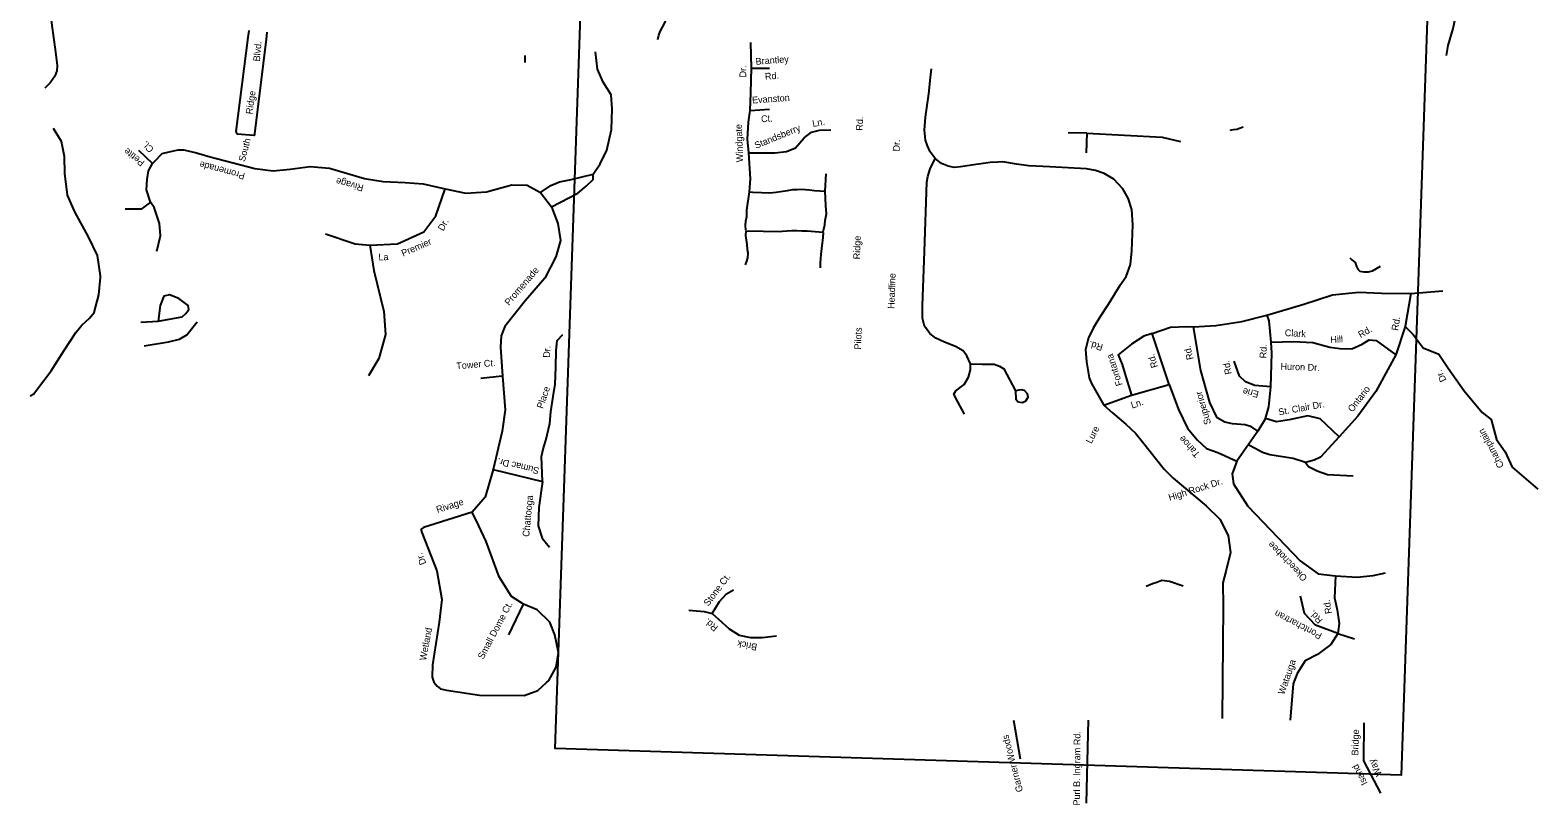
# Model space of a CAD drawing. Extents: x 2308163 to 2335412, y -96774 to 125428.
# Drawn here: x 2317543 to 2321199, y -15693 to -13815 of the extents above; entities that cross this region are included whole.
import ezdxf

# ---------------------------------------------------------------- set-up
doc = ezdxf.new("R2010")
doc.units = 0
for name, color, linetype in [('Old_Level_10', 7, 'Continuous'), ('Old_Level_35', 7, 'Continuous'), ('Old_Level_63', 7, 'Continuous')]:
    doc.layers.add(name, color=color, linetype=linetype)

msp = doc.modelspace()

# ---------------------------------------------------------------- linework, layer by layer
at = {"layer": 'Old_Level_35'}
for p, q in [((2318072, -13833), (2318074.1, -13816.2)), ((2318117.4, -13820.5), (2318115.4, -13837.3)), ((2318743.8, -13893.5), (2318743.3, -13876.6)), ((2319470.7, -14205.2), (2319473.7, -14163.5))]:
    msp.add_line(p, q, dxfattribs=at)
for points in [[(2319065.6, -13837.6), (2319067.4, -13827.6), (2319070.7, -13818.6), (2319081.2, -13799.3), (2319094.4, -13768.8), (2319113.5, -13720.3), (2319131.1, -13670.2), (2319159.1, -13602.4)], [(2317587.9, -13741.7), (2317588.9, -13749.8), (2317595.6, -13803.7), (2317603.9, -13862.2), (2317608.6, -13901.1), (2317608.2, -13914.1), (2317603.3, -13926.6), (2317591.4, -13943.2), (2317578.9, -13955.8)], [(2320978.1, -13876.7), (2320981.8, -13852.3), (2320993.6, -13811.1), (2321000.3, -13780.2), (2321001.8, -13765.2)], [(2318115.4, -13837.3), (2318087.5, -14066.8), (2318087.3, -14068.9), (2318087.1, -14069.7), (2318086.7, -14070.3), (2318086.2, -14070.5), (2318085.4, -14070.7), (2318046.3, -14067.3), (2318044.8, -14066.4), (2318044.1, -14065.3), (2318043.5, -14063.8), (2318043.2, -14062.6), (2318043.1, -14060.8), (2318072, -13833)], [(2319287.7, -14207.5), (2319290.2, -14175.5), (2319285.8, -14112.4), (2319282.9, -14079.2), (2319285.1, -14038.1), (2319289.3, -14010), (2319290.8, -13967.2), (2319292.1, -13907.5), (2319290.7, -13845)], [(2318807.7, -14243.4), (2318871.4, -14210.1), (2318891.4, -14193.1), (2318908.1, -14177.5), (2318908.5, -14164.6), (2318925.5, -14139.4), (2318941.2, -14106), (2318952.6, -14056.3), (2318954.4, -14006.3), (2318952.3, -13972.4), (2318932.4, -13941), (2318918.9, -13909.9), (2318914.4, -13867.9)], [(2319292.1, -13907.5), (2319335.7, -13907.4)], [(2319737.6, -14126.5), (2319725.5, -14110), (2319718.8, -14095.6), (2319714.3, -14081.8), (2319711.7, -14058), (2319714.5, -14026.1), (2319722.5, -13969.8), (2319726.5, -13929.9), (2319727.7, -13916.5), (2319728.6, -13909.2)], [(2319289.3, -14010), (2319336.3, -14006.8)], [(2317713.8, -14410.8), (2317706.8, -14361.1), (2317684.7, -14316.4), (2317651.2, -14256), (2317633.6, -14215.1), (2317627.1, -14162.8), (2317626.2, -14121.3), (2317619.1, -14085.5), (2317600, -14054)], [(2319285.8, -14112.4), (2319349.1, -14112.9), (2319376.9, -14109.2), (2319399.2, -14100.6), (2319420.3, -14076.3), (2319437.6, -14062.4), (2319457.5, -14057.6), (2319484.8, -14057.1)], [(2320105.6, -14065.2), (2320060.4, -14064.2)], [(2320105.6, -14065.2), (2320103.6, -14112.7)], [(2320105.6, -14065.2), (2320288.6, -14074.8), (2320332.9, -14085.5)], [(2320453.2, -14057.8), (2320461.6, -14056.3), (2320469.2, -14055), (2320476, -14052.8), (2320484.7, -14049.4)], [(2317840.2, -14138.6), (2317806.9, -14106.7)], [(2317834.6, -14232), (2317825, -14202.1), (2317827, -14177.3), (2317830.1, -14156), (2317840.2, -14138.6), (2317845.1, -14132.9), (2317863.6, -14114.5), (2317880.3, -14110.4), (2317901.8, -14105.2), (2317916, -14105.7), (2317946.6, -14112.7), (2317979.5, -14122.1)], [(2317979.5, -14122.1), (2318088.1, -14150.7), (2318132.3, -14156.1), (2318173.8, -14152.6), (2318222.3, -14145.4), (2318269.4, -14150), (2318354.2, -14174.6), (2318399.1, -14182.1), (2318452.2, -14184.9), (2318496.4, -14187.4), (2318549.2, -14200), (2318600, -14210.6), (2318649.4, -14207.4), (2318711.1, -14189.9), (2318748.5, -14191.2), (2318780.4, -14209), (2318807.7, -14243.4), (2318823.1, -14284.3), (2318829.5, -14324.9), (2318818.3, -14364.8), (2318790.9, -14416.1), (2318744.7, -14470.6), (2318694.3, -14533.8), (2318685.6, -14556.1), (2318683.7, -14583.6), (2318688.2, -14653.7), (2318695.2, -14735.6), (2318687.5, -14787.5), (2318665.6, -14880.3), (2318646.5, -14947.5), (2318614.7, -14983.8), (2318497.2, -15021.1), (2318491.2, -15024.9), (2318491.1, -15027.8), (2318492.9, -15032.8), (2318529.1, -15125.6), (2318541.5, -15194.9), (2318534.6, -15249.8), (2318519.2, -15353.6), (2318518.2, -15383.1), (2318521.7, -15396), (2318530.3, -15405.2), (2318537.9, -15411.4), (2318552.6, -15414.8), (2318632.9, -15427.4), (2318741.3, -15428.2), (2318774.2, -15415.6), (2318795.5, -15396.6), (2318800.6, -15391.9), (2318818.5, -15359), (2318824.6, -15323.8), (2318815.3, -15281.1), (2318803.5, -15250.2), (2318773, -15220.6), (2318739.1, -15206.7), (2318710.1, -15187.9), (2318680.3, -15140.6), (2318648.7, -15054.9), (2318631.3, -15016.9), (2318614.7, -14983.8)], [(2319823.1, -14623.7), (2319814.7, -14604.3), (2319805.9, -14592.6), (2319786.7, -14581.9), (2319760.1, -14571.9), (2319739.1, -14561.8), (2319724.7, -14550.4), (2319712.3, -14533), (2319706.8, -14513.7), (2319707, -14482.8), (2319712, -14351.6), (2319717.8, -14184.1), (2319720, -14170.3), (2319725.4, -14151.3), (2319737.6, -14126.5)], [(2320185.7, -14434.5), (2320200.9, -14412.5), (2320211.3, -14383.3), (2320214.4, -14350.2), (2320217.1, -14287.5), (2320214.7, -14249.8), (2320206.2, -14222.5), (2320193.2, -14200.1), (2320170.8, -14176.1), (2320148, -14162.8), (2320126.3, -14155.1), (2320104.4, -14151.2), (2320016.1, -14146.3), (2319965.3, -14143.9), (2319935.3, -14139.7), (2319902.2, -14134.8), (2319890, -14135), (2319871.1, -14136.3), (2319831.2, -14141.4), (2319799.2, -14146.8), (2319783.5, -14148.2), (2319769.3, -14145.1), (2319753.3, -14138.7), (2319737.6, -14126.5)], [(2318780.4, -14209), (2318805.8, -14191.7), (2318827.1, -14182.8), (2318854.8, -14177.3), (2318908.5, -14164.6)], [(2318259.4, -14309.3), (2318331.4, -14333.5), (2318366.8, -14336.7), (2318433.9, -14333.1), (2318497.9, -14303.8), (2318526.8, -14265.4), (2318549.2, -14200)], [(2319279, -14300.2), (2319278.2, -14289.1), (2319278.6, -14278.1), (2319281, -14266.8), (2319280.7, -14251.4), (2319287.7, -14207.5)], [(2319287.7, -14207.5), (2319296, -14207.8), (2319316.5, -14208.9), (2319336.9, -14209.6), (2319352, -14208.2), (2319363, -14206.6), (2319379.7, -14203.6), (2319392.8, -14201.7), (2319403, -14201.7), (2319411.3, -14200.8), (2319423.5, -14201.6), (2319433, -14202.3), (2319445.1, -14203.9), (2319470.7, -14205.2)], [(2319466.5, -14304.3), (2319470.6, -14287.1), (2319471, -14276.9), (2319473.9, -14260.4), (2319473, -14240.3), (2319470.7, -14205.2)], [(2317850.6, -14351.1), (2317859.1, -14313.5), (2317856.5, -14283.7), (2317843.6, -14245.4), (2317834.6, -14232), (2317812.7, -14249.1), (2317773.5, -14248.9)], [(2319277.5, -14384.1), (2319281.2, -14375.1), (2319283.4, -14367.3), (2319284.6, -14355.5), (2319282.5, -14346.8), (2319281.8, -14334.5), (2319279, -14313.2), (2319279.8, -14301.8)], [(2319280.6, -14301.4), (2319361.3, -14303), (2319367.2, -14302.4), (2319390.5, -14300.9), (2319402.4, -14300.9), (2319414.6, -14301.7), (2319427.2, -14301.7), (2319466.5, -14304.7)], [(2319459.4, -14391.5), (2319459.8, -14380.1), (2319460.2, -14368.7), (2319461.1, -14359.2), (2319463.1, -14344.7), (2319466.4, -14317.7), (2319467.2, -14305.5)], [(2318366.8, -14336.7), (2318376.5, -14398), (2318400.6, -14497.3), (2318404.6, -14552.6), (2318388.8, -14611.1), (2318363.7, -14653.5)], [(2320743.6, -14367.5), (2320748.6, -14371.8), (2320756, -14378.8), (2320759.7, -14388.1), (2320762.5, -14394.9), (2320767.5, -14399.4), (2320777, -14401.2), (2320788.3, -14401.3), (2320798.4, -14398.3), (2320817.5, -14387.6)], [(2317543.1, -14701.4), (2317552.1, -14696.6), (2317561.1, -14684.5), (2317593.8, -14640.9), (2317624.6, -14592.3), (2317653.9, -14548.1), (2317668.3, -14530.5), (2317687.1, -14513), (2317698.1, -14499.4), (2317709.9, -14456.9), (2317713.7, -14414.9), (2317713.8, -14410.8)], [(2320185.7, -14434.5), (2320157.1, -14480.6), (2320137.2, -14510.7), (2320121.2, -14537.7), (2320109.6, -14561.2), (2320102.6, -14589.1), (2320104.6, -14619.3), (2320111.3, -14657.7), (2320116.8, -14672), (2320146.9, -14724.4), (2320167.6, -14743), (2320199.9, -14770.3), (2320223.2, -14792.2), (2320240.6, -14812.9), (2320292.8, -14879.1), (2320314.6, -14901.2), (2320395.2, -14968), (2320428, -15000.5), (2320448, -15040.1), (2320454.1, -15081.7), (2320443.8, -15124), (2320435.2, -15155.1), (2320435.8, -15211.6), (2320433.7, -15483.4)], [(2317811.3, -14523), (2317853.6, -14520.6), (2317911.7, -14509.8), (2317920.6, -14502.3), (2317927.9, -14492.5), (2317926.5, -14482.3), (2317903.4, -14466), (2317881.1, -14456.4), (2317867.5, -14460.2), (2317858.5, -14482.4)], [(2320263.7, -14550.5), (2320308.4, -14535.5), (2320348.3, -14533.3), (2320364, -14534.4), (2320418.8, -14531.1), (2320481.5, -14521.1), (2320541.7, -14506.3), (2320632.2, -14479.6), (2320701.5, -14457.2), (2320765.4, -14450.5), (2320819.9, -14452.5), (2320891.4, -14453.2)], [(2320891.4, -14453.2), (2320877.6, -14533.3), (2320854.9, -14602.5), (2320806.2, -14691.4), (2320762.4, -14750.7), (2320717.2, -14801.1), (2320672.2, -14849.9), (2320657.2, -14857.8), (2320635.8, -14863.3), (2320605.9, -14853.6), (2320549.6, -14844.8), (2320531.5, -14839.3), (2320513.4, -14829.4), (2320497.2, -14820.3)], [(2320891.4, -14453.2), (2320968.6, -14447.4)], [(2317858.5, -14482.4), (2317853.6, -14520.6)], [(2320552.8, -14571.8), (2320547.5, -14520.1), (2320543, -14505.9)], [(2317819.5, -14580.4), (2317878.9, -14570.4), (2317905.5, -14564.3), (2317923.1, -14553.6), (2317948.4, -14522.2)], [(2320305.5, -14674), (2320263.7, -14550.5), (2320243.6, -14557), (2320213.5, -14576.1), (2320181.8, -14602), (2320191, -14625.5), (2320200, -14655.9), (2320213.6, -14700.3)], [(2320520.5, -14787.4), (2320504.6, -14776.5), (2320489.6, -14771.5), (2320458.5, -14769.5), (2320440.1, -14765.6), (2320422, -14754.6), (2320403.6, -14717.5), (2320382.4, -14639.8), (2320364, -14534.4)], [(2320877.6, -14533.3), (2320896.8, -14553), (2320921.3, -14585.1), (2320959.3, -14601), (2320982, -14634.8), (2321020.5, -14689.3), (2321064.5, -14742.1), (2321085.9, -14759.3), (2321098.9, -14807.4), (2321119.9, -14837.5), (2321136.9, -14874.7), (2321199.3, -14928.2)], [(2318785.2, -14909.3), (2318783.2, -14848.7), (2318788, -14827.3), (2318794, -14810), (2318803.5, -14768.6), (2318805.8, -14740.5), (2318811.2, -14703), (2318816.2, -14673.5), (2318817.6, -14631.9), (2318819, -14592.9), (2318821.2, -14567.4), (2318835.2, -14553.1)], [(2320717.2, -14801.1), (2320671.8, -14757.2), (2320641.9, -14750.3), (2320596, -14759.6), (2320565.2, -14764.5), (2320539.2, -14756.7), (2320547.3, -14728.6), (2320551.5, -14680), (2320554.6, -14597.9), (2320552.8, -14571.8)], [(2320552.8, -14571.8), (2320605.8, -14570), (2320654, -14572.7), (2320694.8, -14583.9), (2320719.2, -14586.9), (2320747.9, -14587.4), (2320773.3, -14576.3), (2320789.9, -14566), (2320807.3, -14567.2), (2320854.9, -14602.5)], [(2319808.8, -14745.7), (2319792.7, -14716), (2319783.3, -14697.6), (2319787.6, -14689.8), (2319808.2, -14674.4), (2319818.9, -14656.7), (2319823.5, -14638.8), (2319823.1, -14623.7)], [(2319823.1, -14623.7), (2319852, -14624.5), (2319880.6, -14625.2), (2319893.4, -14629.4), (2319904.1, -14636.2), (2319932.3, -14689.6), (2319933.3, -14709.7), (2319938.9, -14715.9), (2319949.3, -14717.9), (2319958, -14713.6), (2319963.5, -14705), (2319961.6, -14697.1), (2319954.1, -14688.6), (2319946.3, -14687), (2319936.3, -14688.4), (2319932.3, -14689.6)], [(2320551.5, -14680), (2320513.1, -14676.7), (2320490.4, -14667.4), (2320476.1, -14653.7), (2320463, -14617.8)], [(2318636.3, -14658.5), (2318688.1, -14652.9)], [(2320213.6, -14700.3), (2320305.5, -14674)], [(2320305.5, -14674), (2320327.8, -14735), (2320350.1, -14779.8), (2320373, -14808.1), (2320396.1, -14829), (2320423.2, -14839.1), (2320469, -14860.2)], [(2320146.9, -14724.4), (2320213.6, -14700.3)], [(2320539.2, -14756.7), (2320520.5, -14787.4), (2320469, -14860.2), (2320458.1, -14890.9), (2320461, -14914.8), (2320495.8, -14969.2), (2320623.3, -15101.9), (2320666.2, -15132.7), (2320708.2, -15137.8), (2320761.3, -15141.5), (2320800, -15137.3), (2320829.5, -15131)], [(2318665.6, -14880.3), (2318785.2, -14909.3), (2318776.3, -14972.2), (2318774.8, -15016.5), (2318784.5, -15046.5), (2318802.6, -15068.6)], [(2320635.8, -14863.3), (2320643.1, -14872.6), (2320664, -14883.4), (2320689.5, -14892.4), (2320751.4, -14895.5)], [(2319196.9, -15229), (2319214.6, -15200), (2319232, -15181.3), (2319249.1, -15171.6)], [(2320249.2, -15163), (2320265, -15156.1), (2320275.4, -15152.9), (2320287.5, -15148.7), (2320306.1, -15151.1), (2320339, -15162.5)], [(2320708.2, -15137.8), (2320706.4, -15190.9), (2320712.7, -15220.4), (2320717.1, -15253.6), (2320714.4, -15277.3), (2320697, -15304.2), (2320665, -15328.8), (2320635.1, -15344.2), (2320615.7, -15374.7), (2320605.6, -15400), (2320598.9, -15487.9)], [(2318703.7, -15280.5), (2318739.1, -15206.7)], [(2320714.4, -15277.3), (2320660.1, -15257.8), (2320633.5, -15229.4), (2320624, -15187)], [(2319140.5, -15220.7), (2319177.7, -15224.5), (2319196.9, -15229), (2319220.6, -15250.5), (2319238.1, -15266.5), (2319262.1, -15281.5), (2319290.2, -15287.6), (2319318.6, -15287.3), (2319353.1, -15283)], [(2320714.4, -15277.3), (2320754.3, -15290.4)], [(2319945, -15582.2), (2319928.2, -15488.5)], [(2320104.5, -15688.5), (2320109.4, -15487.4)], [(2320818.4, -15664.7), (2320777.1, -15586.3), (2320778.4, -15493.8)]]:
    msp.add_lwpolyline(points, dxfattribs=at)
at = {"layer": 'Old_Level_63'}
msp.add_lwpolyline([(2320981.2, -12335.3), (2320867.9, -15621.3), (2318816.5, -15556.5), (2318948.8, -11722.3)], dxfattribs=at)

# ---------------------------------------------------------------- texts
at = {"layer": 'Old_Level_10'}
for s, height, rotation, p in [('Blvd.', 16.4, 85.2272, (2318100.3, -13891.6)), ('Brantley', 16.4, 4.3646, (2319303, -13899.4)), ('Dr.', 16.4, 89.4385, (2319279.5, -13930)), ('Rd.', 16.4, 4.3646, (2319325.6, -13935.6)), ('Ridge', 16.4, 81.8623, (2318082, -14020)), ('Evanston', 16.4, 3.9715, (2319294.3, -13993.1)), ('Ct.', 16.4, 3.9715, (2319316.1, -14038.7)), ('Ln.', 16.4, 10.8306, (2319441.5, -14050.1)), ('Rd.', 16.4, 87.9298, (2319561.9, -14059.2)), ('Windgate', 16.4, 92.2238, (2319272.3, -14135.1)), ('Standsberry', 16.404, 22.4236, (2319303.7, -14103.2)), ('Petite', 16.4, 141.9823, (2317822.3, -14133.9)), ('Ct.', 16.4, 134.3578, (2317844.3, -14102.7)), ('South ', 16.4, 75.4775, (2318063.8, -14135.1)), ('Dr.', 16.4, 87.0673, (2319651.5, -14109.6)), ('Promenade', 16.4, 164.8185, (2318065.3, -14162.1)), ('Rivage ', 16.4, 164.9249, (2318353, -14190.8)), ('Dr.', 16.4, 61.5716, (2318545, -14303.4)), ('Premier ', 16.4, 23.573, (2318447.7, -14364.3)), ('Ridge', 16.4, 88.0247, (2319555.4, -14371)), ('La ', 16.4, 2.8628, (2318388.1, -14373.6)), ('Promenade', 16.4, 49.5056, (2318704.4, -14484)), ('Headline', 16.4, 88.0247, (2319639, -14491)), ('Rd.', 16.4, 80.9562, (2320860.3, -14544.5)), ('Pilots', 16.4, 87.8633, (2319557.9, -14589.6)), ('Clark', 16.4, 356.6269, (2320585.2, -14556.6)), ('Rd.', 16.4, 29.8603, (2320769.4, -14562)), ('Dr.', 16.4, 87.4369, (2318803.4, -14609.6)), ('Rd.', 16.4, 164.5659, (2320145.9, -14577.2)), ('Rd.', 16.4, 103.6352, (2320364.4, -14612.2)), ('Rd.', 16.4, 87.8778, (2320540.8, -14611)), ('Hill', 16.4, 3.1309, (2320696.6, -14573.6)), ('Tower Ct.', 16.4, 4.9538, (2318577.2, -14637.4)), ('Fontana', 16.4, 107.7984, (2320192.6, -14674.8)), ('Rd.', 16.4, 106.6838, (2320278.2, -14631.2)), ('Rd.', 16.4, 101.3226, (2320457.2, -14648.1)), ('Huron Dr.', 16.4, 358.0247, (2320575, -14638.1)), ('Dr.', 16.4, 116.2723, (2320978.2, -14663.2)), ('Place', 16.4, 71.0915, (2318786.5, -14733.9)), ('Superior', 16.4, 106.4077, (2320407.1, -14768.6)), ('Erie', 16.4, 167.3506, (2320523.8, -14690.7)), ('Ontario', 16.4, 52.5914, (2320749.9, -14742.4)), ('Ln.', 16.4, 18.5093, (2320215.5, -14732.6)), ('St. Clair Dr.', 16.404, 10.3937, (2320571.7, -14749.3)), ('Lure', 16.4, 62.5274, (2320116.6, -14819)), ('Tahoe', 16.4, 132.3947, (2320381.2, -14842.3)), ('Champlain', 16.4, 118.4032, (2321117.8, -14871.4)), ('Sumac Dr.', 16.4, 166.5432, (2318778.7, -14876.1)), ('High Rock Dr.', 16.404, 17.5209, (2320306.5, -14956.4)), ('Rivage ', 16.4, 17.4763, (2318530.8, -14985.6)), ('Chattooga', 16.4, 84.5243, (2318753.2, -15043.9)), ('Okeechobee', 16.4, 134.2898, (2320641.3, -15141.7)), ('Dr.', 16.4, 112.2366, (2318504.2, -15107.5)), ('Stone Ct.', 16.4, 52.9539, (2319187.7, -15212.8)), ('Small Dome Ct.', 16.404, 62.207, (2318642, -15341.5)), ('Rd.', 16.4, 99.3895, (2320700.1, -15228.7)), ('Rd.', 16.4, 140.7679, (2319212.9, -15261.4)), ('Pontchartran', 16.404, 152.5317, (2320677.3, -15278.4)), ('Rd.', 16.4, 134.4566, (2320679, -15244.1)), ('Wetland', 16.4, 79.2672, (2318503.1, -15344.2)), ('Brick', 16.4, 169.0975, (2319307.2, -15303.3)), ('Watauga', 16.4, 70.8529, (2320584.1, -15427.1)), ('Garner Woods', 16.404, 104.4911, (2319950.9, -15659.8)), ('Purl B. Ingram Rd.', 16.404, 89.5734, (2320088.9, -15694.7)), ('Bridge', 16.4, 88.4171, (2320763.8, -15573.5)), ('Isand', 16.4, 117.301, (2320787, -15640.5)), ('Way', 16.4, 117.301, (2320822, -15618.9))]:
    msp.add_text(s, height=height, rotation=rotation, dxfattribs=at).set_placement(p)

doc.saveas('drawing.dxf')
